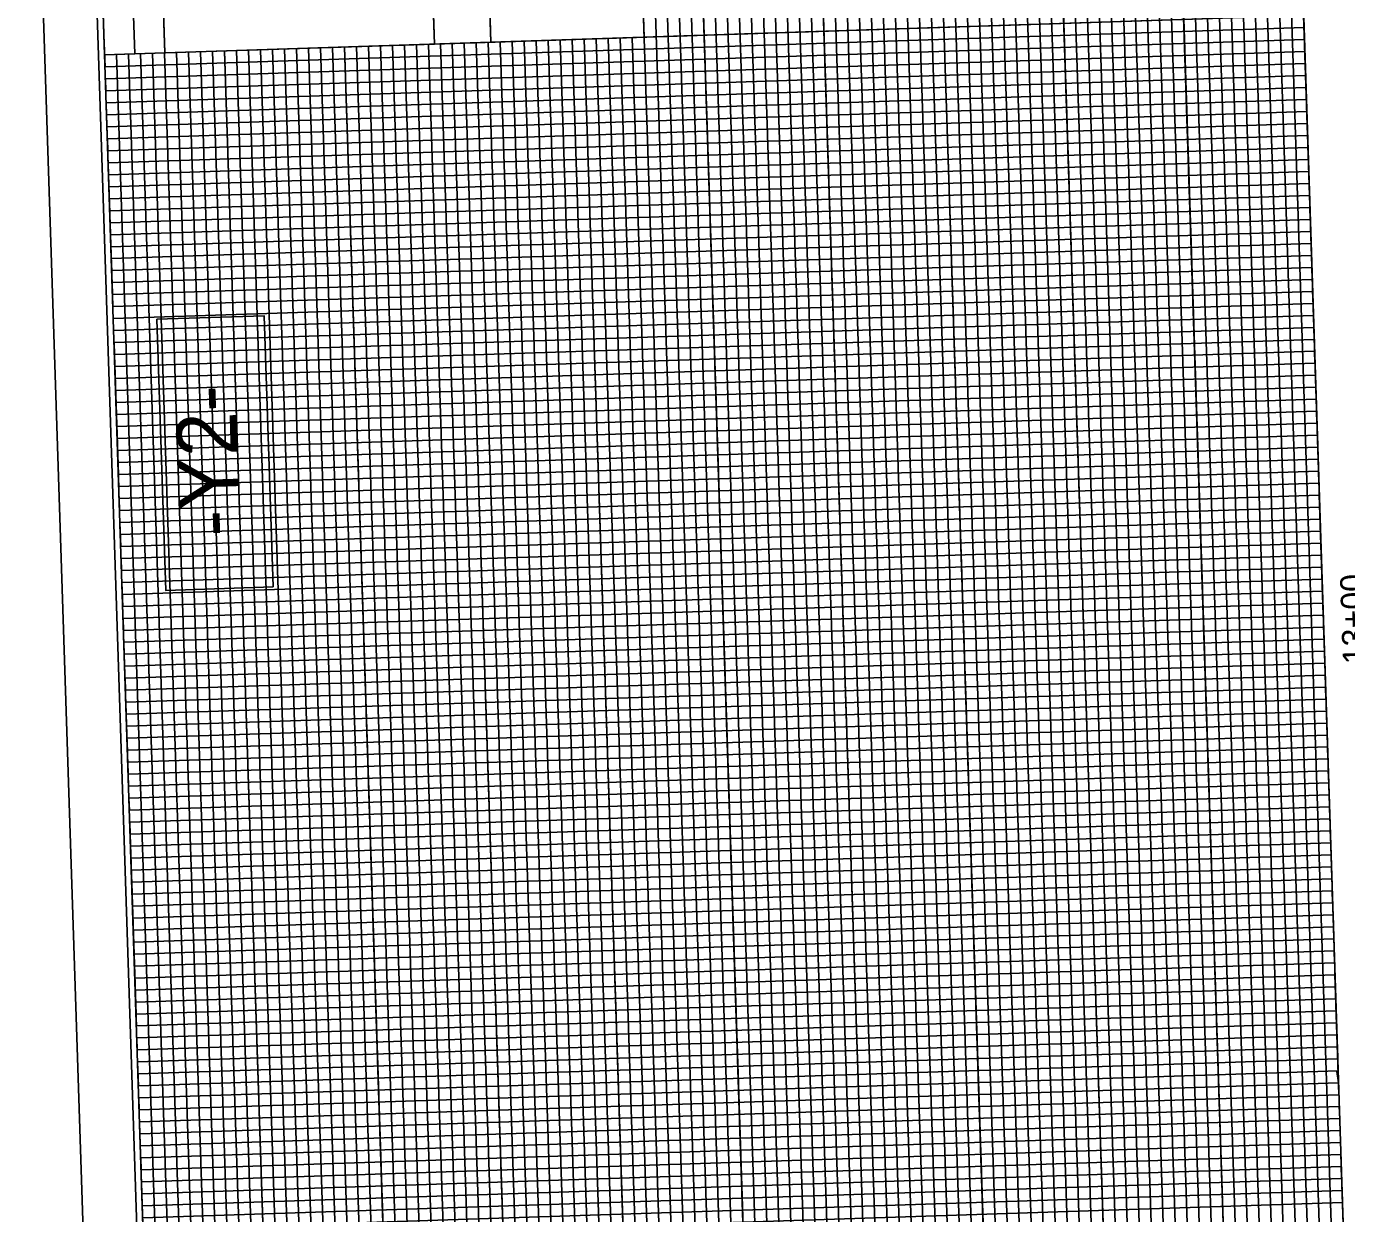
# Model space of a CAD drawing. Extents: x 1627314 to 1628469, y 762309 to 764230.
# Drawn here: x 1627314 to 1627864, y 763293 to 763788 of the extents above; entities that cross this region are included whole.
import ezdxf

# ---------------------------------------------------------------- set-up
doc = ezdxf.new("R2010")
doc.units = 0
for name, color, linetype in [('Exist Vertical Profile Horizontal Axis Label Major', 7, 'Continuous'), ('Old_Level_2', 7, 'Continuous'), ('Prop Grid Mask', 7, 'Continuous'), ('Sheet Data Field CELL', 7, 'Continuous'), ('Sheet DOT Grid CELL', 7, 'Continuous'), ('Sheet Layout Profile Border Port 1', 7, 'Continuous'), ('Sheet Plot Border Inside CELL', 7, 'Continuous'), ('Sheet Plot Border Outside CELL', 7, 'Continuous'), ('Sheet Profile CELL', 7, 'Continuous'), ('Sheet Profile Grid Major CELL', 7, 'Continuous'), ('Sheet Profile Grid Middle CELL', 7, 'Continuous'), ('Sheet Profile Grid Minor CELL', 7, 'Continuous'), ('Sheet Sticker Exception Certification CELL', 7, 'Continuous')]:
    doc.layers.add(name, color=color, linetype=linetype)

msp = doc.modelspace()

# ---------------------------------------------------------------- linework, layer by layer
at = {"layer": 'Old_Level_2'}
msp.add_lwpolyline([(1627507.79, 763781.61), (1627501.25, 763981.49), (1627565.16, 763983.58), (1627571.7, 763783.7)], close=True, dxfattribs=at)
at = {"layer": 'Prop Grid Mask'}
msp.add_lwpolyline([(1627417.01, 763554.6), (1627413.31, 763667.62), (1627368.59, 763666.16), (1627372.29, 763553.14)], close=True, dxfattribs=at)
at = {"layer": 'Sheet DOT Grid CELL'}
for p, q in [((1627690.1, 763987.68), (1627739.13, 762488.48)), ((1627740.07, 763989.32), (1627789.11, 762490.12)), ((1627790.04, 763990.95), (1627839.08, 762491.75)), ((1627590.15, 763984.41), (1627639.19, 762485.21)), ((1627640.12, 763986.05), (1627689.16, 762486.85)), ((1627846.55, 763792.69), (1627484.3, 763780.84)), ((1627446.77, 763779.57), (1627489.27, 762480.31)), ((1627496.74, 763781.25), (1627539.24, 762481.95)), ((1627546.72, 763782.83), (1627589.21, 762483.58)), ((1627396.8, 763777.93), (1627439.29, 762478.68)), ((1627848.19, 763742.72), (1627348.46, 763726.37)), ((1627849.82, 763692.75), (1627350.09, 763676.4)), ((1627851.46, 763642.77), (1627351.73, 763626.43)), ((1627853.09, 763592.8), (1627353.36, 763576.45)), ((1627854.73, 763542.83), (1627354.99, 763526.48)), ((1627856.36, 763492.85), (1627356.63, 763476.51)), ((1627858, 763442.88), (1627358.26, 763426.53)), ((1627859.63, 763392.91), (1627359.9, 763376.56)), ((1627861.27, 763342.93), (1627361.53, 763326.59))]:
    msp.add_line(p, q, dxfattribs=at)
at = {"layer": 'Sheet Layout Profile Border Port 1'}
msp.add_lwpolyline([(1627548.65, 762532.28), (1627887.42, 762543.36), (1627841.65, 763942.61), (1627566.8, 763933.62)], dxfattribs=at)
at = {"layer": 'Sheet Plot Border Inside CELL'}
msp.add_lwpolyline([(1628446.34, 762357.53), (1628391.86, 764023.14), (1627337.33, 763988.65), (1627391.81, 762323.04)], close=True, dxfattribs=at)
at = {"layer": 'Sheet Plot Border Outside CELL'}
msp.add_lwpolyline([(1628469.21, 762345.27), (1628413.63, 764044.37), (1627314.22, 764008.4), (1627369.79, 762309.31)], close=True, dxfattribs=at)
at = {"layer": 'Sheet Profile CELL'}
for p, q in [((1627889.05, 762493.39), (1627840.02, 763992.59)), ((1627359.37, 763776.71), (1627352.83, 763976.65))]:
    msp.add_line(p, q, dxfattribs=at)
for points in [[(1627340.28, 763976.24), (1627389.32, 762477.04), (1628438.76, 762511.37), (1628389.72, 764010.57)], [(1627346.82, 763776.3), (1627340.28, 763976.24), (1627365.32, 763977.06), (1627371.86, 763777.12)], [(1627371.86, 763777.12), (1627368.59, 763877.11), (1627481.03, 763880.79), (1627484.3, 763780.79)]]:
    msp.add_lwpolyline(points, close=True, dxfattribs=at)
at = {"layer": 'Sheet Profile Grid Major CELL'}
for points in [[(1627640.12, 763986.05), (1627689.16, 762486.85), (1627739.13, 762488.48), (1627690.1, 763987.68)], [(1627740.07, 763989.32), (1627789.11, 762490.12), (1627789.11, 762490.12), (1627839.08, 762491.75), (1627790.04, 763990.95)], [(1627546.71, 763782.88), (1627589.21, 762483.58), (1627639.19, 762485.21), (1627590.15, 763984.41)], [(1627363.17, 763276.61), (1627361.53, 763326.59), (1627861.27, 763342.93), (1627859.63, 763392.91), (1627359.9, 763376.56), (1627358.26, 763426.53), (1627858, 763442.88), (1627856.36, 763492.85), (1627356.63, 763476.51), (1627354.99, 763526.48), (1627854.73, 763542.83), (1627853.09, 763592.8), (1627353.36, 763576.45), (1627351.73, 763626.43), (1627851.46, 763642.77), (1627849.82, 763692.75), (1627350.09, 763676.4), (1627348.46, 763726.37), (1627848.19, 763742.72), (1627846.55, 763792.69), (1627346.82, 763776.35), (1627345.96, 763802.63)], [(1627439.29, 762478.68), (1627396.79, 763777.98)], [(1627446.77, 763779.62), (1627489.27, 762480.31), (1627539.24, 762481.95), (1627496.74, 763781.25)]]:
    msp.add_lwpolyline(points, dxfattribs=at)
at = {"layer": 'Sheet Profile Grid Middle CELL'}
msp.add_line((1627414.31, 762477.86), (1627371.81, 763777.11), dxfattribs=at)
for points in [[(1627715.08, 763988.5), (1627764.12, 762489.3), (1627814.09, 762490.94), (1627765.06, 763990.13)], [(1627815.03, 763991.77), (1627864.07, 762492.57)], [(1627615.14, 763985.23), (1627664.17, 762486.03), (1627714.15, 762487.67), (1627665.11, 763986.86)], [(1627863.72, 763267.97), (1627862.08, 763317.95), (1627362.35, 763301.6), (1627360.72, 763351.57), (1627860.45, 763367.92), (1627858.81, 763417.89), (1627359.08, 763401.55), (1627357.45, 763451.52), (1627857.18, 763467.87), (1627855.54, 763517.84), (1627355.81, 763501.49), (1627354.18, 763551.47), (1627853.91, 763567.81), (1627852.28, 763617.79), (1627352.54, 763601.44), (1627350.91, 763651.41), (1627850.64, 763667.76), (1627849.01, 763717.73), (1627349.27, 763701.39), (1627347.64, 763751.36), (1627847.37, 763767.71), (1627845.74, 763817.68), (1627570.88, 763808.69)], [(1627521.73, 763782.02), (1627564.23, 762482.76), (1627614.2, 762484.4), (1627570.88, 763808.69)], [(1627421.78, 763778.8), (1627464.28, 762479.49), (1627514.25, 762481.13), (1627471.75, 763780.43)]]:
    msp.add_lwpolyline(points, dxfattribs=at)
at = {"layer": 'Sheet Profile Grid Minor CELL'}
for p, q in [((1627742.5, 762538.62), (1627696.73, 763937.87)), ((1627701.73, 763938.04), (1627747.49, 762538.78)), ((1627752.49, 762538.95), (1627706.72, 763938.2)), ((1627711.72, 763938.36), (1627757.49, 762539.11)), ((1627767.48, 762539.44), (1627721.71, 763938.69)), ((1627726.71, 763938.85), (1627772.48, 762539.6)), ((1627731.71, 763939.02), (1627777.48, 762539.76)), ((1627736.71, 763939.18), (1627782.48, 762539.93)), ((1627792.47, 762540.25), (1627746.7, 763939.51)), ((1627751.7, 763939.67), (1627797.47, 762540.42)), ((1627802.47, 762540.58), (1627756.7, 763939.83)), ((1627761.69, 763940), (1627807.46, 762540.75)), ((1627817.46, 762541.07), (1627771.69, 763940.32)), ((1627776.69, 763940.49), (1627822.45, 762541.24)), ((1627827.45, 762541.4), (1627781.68, 763940.65)), ((1627786.68, 763940.81), (1627832.45, 762541.56)), ((1627842.44, 762541.89), (1627796.67, 763941.14)), ((1627801.67, 763941.3), (1627847.44, 762542.05)), ((1627852.44, 762542.22), (1627806.67, 763941.47)), ((1627811.67, 763941.63), (1627857.44, 762542.38)), ((1627867.43, 762542.71), (1627821.66, 763941.96)), ((1627826.66, 763942.12), (1627872.43, 762542.87)), ((1627877.42, 762543.03), (1627831.66, 763942.29)), ((1627576.79, 763933.95), (1627622.56, 762534.7)), ((1627627.56, 762534.86), (1627581.79, 763934.11)), ((1627586.79, 763934.28), (1627632.56, 762535.02)), ((1627642.55, 762535.35), (1627596.78, 763934.6)), ((1627601.78, 763934.77), (1627647.55, 762535.51)), ((1627652.55, 762535.68), (1627606.78, 763934.93)), ((1627611.77, 763935.09), (1627657.54, 762535.84)), ((1627667.54, 762536.17), (1627621.77, 763935.42)), ((1627626.77, 763935.58), (1627672.53, 762536.33)), ((1627677.53, 762536.5), (1627631.76, 763935.75)), ((1627636.76, 763935.91), (1627682.53, 762536.66)), ((1627692.52, 762536.99), (1627646.75, 763936.24)), ((1627651.75, 763936.4), (1627697.52, 762537.15)), ((1627702.52, 762537.31), (1627656.75, 763936.56)), ((1627661.75, 763936.73), (1627707.52, 762537.48)), ((1627717.51, 762537.8), (1627671.74, 763937.05)), ((1627676.74, 763937.22), (1627722.51, 762537.97)), ((1627727.51, 762538.13), (1627681.74, 763937.38)), ((1627686.73, 763937.55), (1627732.5, 762538.29)), ((1627481.75, 763780.71), (1627522.61, 762531.43)), ((1627486.75, 763780.92), (1627527.61, 762531.59)), ((1627491.74, 763781.09), (1627532.61, 762531.75)), ((1627542.6, 762532.08), (1627501.74, 763781.41)), ((1627506.74, 763781.58), (1627547.6, 762532.25)), ((1627552.6, 762532.41), (1627511.73, 763781.69)), ((1627531.72, 763782.34), (1627572.59, 762533.06)), ((1627577.59, 762533.23), (1627536.72, 763782.51)), ((1627556.71, 763783.16), (1627597.57, 762533.88)), ((1627602.57, 762534.04), (1627561.71, 763783.33)), ((1627392.68, 762527.18), (1627351.82, 763776.51)), ((1627356.82, 763776.67), (1627398.03, 762527.35)), ((1627402.68, 762527.5), (1627361.81, 763776.84))]:
    msp.add_line(p, q, dxfattribs=at)
for points in [[(1627836.65, 763942.45), (1627882.42, 762543.2)], [(1627566.71, 763783.49), (1627607.57, 762534.21), (1627617.56, 762534.53), (1627571.79, 763933.79)], [(1627850.15, 763682.75), (1627849.99, 763687.75), (1627350.25, 763671.4), (1627349.93, 763681.4), (1627849.66, 763697.74), (1627849.5, 763702.74), (1627349.76, 763686.39), (1627349.6, 763691.39), (1627849.33, 763707.74), (1627849.17, 763712.74), (1627349.44, 763696.39), (1627349.11, 763706.38), (1627848.84, 763722.73), (1627848.68, 763727.73), (1627348.95, 763711.38), (1627348.78, 763716.38), (1627848.52, 763732.72), (1627848.35, 763737.72), (1627348.62, 763721.38), (1627348.29, 763731.37), (1627848.03, 763747.72), (1627847.86, 763752.71), (1627348.13, 763736.37), (1627347.97, 763741.37), (1627847.7, 763757.71), (1627847.53, 763762.71), (1627347.8, 763746.36), (1627347.48, 763756.36), (1627847.21, 763772.7), (1627847.04, 763777.7), (1627347.31, 763761.35), (1627347.15, 763766.35), (1627846.88, 763782.7), (1627846.72, 763787.7), (1627346.98, 763771.35), (1627346.66, 763781.34)], [(1627391.8, 763777.82), (1627432.66, 762528.49), (1627442.66, 762528.81), (1627401.79, 763778.14)], [(1627406.79, 763778.31), (1627447.65, 762528.98), (1627452.65, 762529.14), (1627411.79, 763778.47)], [(1627416.78, 763778.63), (1627457.65, 762529.3), (1627467.64, 762529.63), (1627426.78, 763778.96)], [(1627431.78, 763779.13), (1627472.64, 762529.79), (1627477.64, 762529.96), (1627436.77, 763779.29)], [(1627441.77, 763779.45), (1627482.64, 762530.12), (1627492.63, 762530.45), (1627451.77, 763779.78)], [(1627456.86, 763779.95), (1627497.72, 762530.71), (1627502.62, 762530.87), (1627461.76, 763780.11)], [(1627466.76, 763780.27), (1627507.62, 762530.94), (1627517.62, 762531.26), (1627476.75, 763780.6)], [(1627516.73, 763781.85), (1627557.6, 762532.57), (1627567.59, 762532.9), (1627526.73, 763782.18)], [(1627541.72, 763782.67), (1627582.58, 762533.39), (1627592.58, 762533.72), (1627551.71, 763783)], [(1627366.81, 763777), (1627407.68, 762527.67), (1627417.67, 762528), (1627376.81, 763777.33)], [(1627381.8, 763777.44), (1627422.67, 762528.16), (1627427.67, 762528.32), (1627386.8, 763777.65)], [(1627860.12, 763377.91), (1627360.39, 763361.57), (1627360.23, 763366.57), (1627859.96, 763382.91), (1627859.79, 763387.91), (1627360.06, 763371.56), (1627359.73, 763381.56), (1627859.47, 763397.9), (1627859.3, 763402.9), (1627359.57, 763386.55), (1627359.41, 763391.55), (1627859.14, 763407.9), (1627858.98, 763412.9), (1627359.24, 763396.55), (1627358.92, 763406.54), (1627858.65, 763422.89), (1627858.49, 763427.89), (1627358.75, 763411.54), (1627358.59, 763416.54), (1627858.32, 763432.88), (1627858.16, 763437.88), (1627358.43, 763421.54), (1627358.1, 763431.53), (1627857.83, 763447.88), (1627857.67, 763452.87), (1627357.94, 763436.53), (1627357.77, 763441.53), (1627857.51, 763457.87), (1627857.34, 763462.87), (1627357.61, 763446.52), (1627357.28, 763456.52), (1627857.02, 763472.86), (1627856.85, 763477.86), (1627357.12, 763461.51), (1627356.96, 763466.51), (1627856.69, 763482.86), (1627856.53, 763487.86), (1627356.79, 763471.51), (1627356.47, 763481.5), (1627856.2, 763497.85), (1627856.03, 763502.85), (1627356.3, 763486.5), (1627356.14, 763491.5), (1627855.87, 763507.84), (1627855.71, 763512.84), (1627355.98, 763496.5), (1627355.65, 763506.49), (1627855.38, 763522.84), (1627855.22, 763527.83), (1627355.48, 763511.49), (1627355.32, 763516.49), (1627855.05, 763532.83), (1627854.89, 763537.83), (1627355.16, 763521.48), (1627354.83, 763531.48), (1627854.56, 763547.82), (1627854.4, 763552.82), (1627354.67, 763536.47), (1627354.5, 763541.47), (1627854.24, 763557.82), (1627854.07, 763562.82), (1627354.34, 763546.47), (1627354.01, 763556.46), (1627853.75, 763572.81), (1627853.58, 763577.81), (1627353.85, 763561.46), (1627353.69, 763566.46), (1627853.42, 763582.8), (1627853.26, 763587.8), (1627353.52, 763571.46), (1627353.2, 763581.45), (1627852.93, 763597.8), (1627852.77, 763602.79), (1627353.03, 763586.45), (1627352.87, 763591.45), (1627852.6, 763607.79), (1627852.44, 763612.79), (1627352.71, 763596.44), (1627352.38, 763606.44), (1627852.11, 763622.78), (1627851.95, 763627.78), (1627352.22, 763611.43), (1627352.05, 763616.43), (1627851.78, 763632.78), (1627851.62, 763637.78), (1627351.89, 763621.43), (1627351.56, 763631.42), (1627851.29, 763647.77), (1627851.13, 763652.77), (1627351.4, 763636.42), (1627351.23, 763641.42), (1627850.97, 763657.76), (1627850.8, 763662.76), (1627351.07, 763646.42), (1627350.74, 763656.41), (1627850.48, 763672.76), (1627850.31, 763677.75), (1627350.58, 763661.41), (1627350.42, 763666.41), (1627850.15, 763682.75)], [(1627362.68, 763291.61), (1627862.41, 763307.95), (1627862.25, 763312.95), (1627362.51, 763296.6), (1627362.19, 763306.6), (1627861.92, 763322.94), (1627861.76, 763327.94), (1627362.02, 763311.59), (1627361.86, 763316.59), (1627861.59, 763332.94), (1627861.43, 763337.94), (1627361.7, 763321.59), (1627361.37, 763331.58), (1627861.1, 763347.93), (1627860.4, 763352.61), (1627860.94, 763352.93), (1627361.21, 763336.58), (1627361.04, 763341.58), (1627860.78, 763357.93), (1627860.61, 763362.92), (1627360.88, 763346.58), (1627360.55, 763356.57), (1627860.28, 763372.92), (1627860.12, 763377.91)], [(1627363, 763281.61), (1627862.74, 763297.96), (1627862.57, 763302.95), (1627362.84, 763286.61)]]:
    msp.add_lwpolyline(points, dxfattribs=at)
at = {"layer": 'Sheet Sticker Exception Certification CELL'}
for p, q in [((1627484.3, 763780.79), (1627477.76, 763980.72)), ((1627484.3, 763780.79), (1627477.76, 763980.72)), ((1627501.25, 763981.49), (1627507.79, 763781.56)), ((1627501.25, 763981.49), (1627507.79, 763781.56)), ((1627507.79, 763781.56), (1627484.3, 763780.79)), ((1627507.79, 763781.56), (1627484.3, 763780.79))]:
    msp.add_line(p, q, dxfattribs=at)

# ---------------------------------------------------------------- texts
at = {"layer": 'Exist Vertical Profile Horizontal Axis Label Major'}
msp.add_text('13+00', height=10, rotation=91.8735, dxfattribs=at).set_placement((1627872.9, 763522.58))
at = {"layer": 'Sheet Data Field CELL'}
msp.add_text('-Y2-', height=25, rotation=91.8735, dxfattribs=at).set_placement((1627403.25, 763575.89))

doc.saveas('drawing.dxf')
